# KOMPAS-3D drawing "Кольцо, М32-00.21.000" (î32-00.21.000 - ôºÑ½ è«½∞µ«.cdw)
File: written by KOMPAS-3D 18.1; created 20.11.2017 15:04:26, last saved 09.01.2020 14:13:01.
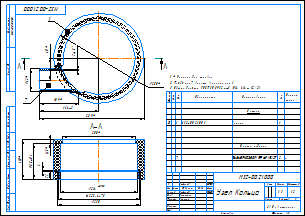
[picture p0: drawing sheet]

Sheet 1: A3, landscape

Document properties: Автор: Милов; Организация: Милов; Масса: 1.30083; Полное имя файла: М32-00.21.000 - Узел Кольцо.a3d

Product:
- Part/product: (unnamed)  | designation М32-00.21.000-01
- Part/product: Кольцо  | designation М32-00.21.000
    Масса: 1.60884
  - Component [detail]: Труба 63 PN10 S=5,8 FV PPR ф. FV PLAST  | pos. 7  | Материал: Полипропилен  ГОСТ 26996-86 (density 900 kg/m3); Масса: 0.0799362; Раздел спецификации: Прочие изделия; Примечание: м; source file: ..\..\..\..\1 ПКИ 3D\Полипропиленовые фитинги, трубы\Трубы\Труба 63 PN10 S=5,8 FV PPR ф. FV PLAST.m3d
  - Component [detail]: Кольцо  | designation М32-00.21.001  | pos. 8  | Материал: Полипропилен  ГОСТ 26996-86 (density 900 kg/m3); Масса: 1.5289; Раздел спецификации: Детали; source file: М32-00.21.001 - Кольцо.cdw, М32-00.21.001 - Кольцо.m3d
- Part/product: Узел Кольцо  | designation М32-00.21.000
    Масса: 1.30083
    source file: М32-00.21.000 - Кольцо.cdw, М32-00.21.000-01 - Кольцо.cdw
  - Component [detail]: Труба 63 PN10 S=5,8 FV PPR ф. FV PLAST  | pos. 9  | Материал: Полипропилен  ГОСТ 26996-86 (density 900 kg/m3); Масса: 0.0740283; Раздел спецификации: Прочие изделия; Примечание: м; source file: ..\..\..\..\1 ПКИ 3D\Полипропиленовые фитинги, трубы\Трубы\Труба 63 PN10 S=5,8 FV PPR ф. FV PLAST.m3d
  - Component [detail]: Кольцо  | designation М32-00.21.001  | pos. 10  | Материал: Полипропилен  ГОСТ 26996-86 (density 900 kg/m3); Масса: 1.66598; Раздел спецификации: Детали; Форматы листов документа: A3; source file: М32-00.21.001 - Кольцо.cdw, М32-00.21.001 - Кольцо.m3d
- Part/product: Кольцо  | designation М32-00.21.000  | pos. 0
    Масса: 1.28716
    Раздел спецификации: Сборочные единицы
    Форматы листов документа: A3
    source file: М32-00.21.000 - Кольцо.cdw
  - Component [detail]: Деталь  | pos. 4  | Масса: 0.0160222; Раздел спецификации: Детали; source file: ..\Стержень для позиционирования корпуса.m3d
  - Component [detail]: Труба 63 PN10 S=5,8 FV PPR ф. FV PLAST  | designation 1003  | pos. 0  | Материал: Полипропилен  ГОСТ 26996-86 (density 900 kg/m3); Масса: 0.152669; Раздел спецификации: Прочие изделия; Примечание: м
  - Component [detail]: Кольцо  | designation М40-00.21.001  | pos. 0  | Материал: Полипропилен  ГОСТ 26996-86 (density 900 kg/m3); Масса: 1.59002; Раздел спецификации: Детали; Форматы листов документа: A3; source file: ..\Магна ins 40\3Д\М40-00.21.001 - Кольцо.cdw, М32-00.21.001 - Кольцо.m3d

Title block, sheet 1: Наименование: Узел Кольцо; designation: М32-00.21.000; Масса: 1,3; scale: 1:2; Количество листов документа: 1; organisation: ЗАО «Астерион»; Форматы листов документа: A3; stored path: D:\Отработать\Магна 40\Чертежи\М40-00.21.000 - Кольцо.cdw; Разработал: Лифлянд; Проверил: Борисенко; Т. контр.: Лучихин; Разработал, date: 19.04.2019

Views: Проекционный вид 3, Местный разрез 1, Вид 4, Разрез А-А, Вид:1
Referenced files in D:\Magna\Магна Ins\Магна ins 32\Для Караби\: М32-00.21.000 - Узел Кольцо.a3d, М32-00.21.001 - Кольцо.m3d, М32-00.21.001 - Кольцо.cdw
Referenced files in D:\Отработать\Магна 40\3Д\: М40-00.21.000 - Кольцо.a3d
Referenced files in Z:\Магна\Магна Ins\Магна ins 32\: М32-00.21.000 - Кольцо.a3d, М32-00.21.001 - Кольцо.m3d
Referenced files in D:\1 ПКИ 3D\Полипропиленовые фитинги, трубы\Трубы\: Труба 63 PN10 S=5,8 FV PPR ф. FV PLAST.m3d
Referenced files in Z:\1 ПКИ 3D\Полипропиленовые фитинги, трубы\Трубы\: Труба 63 PN10 S=5,8 FV PPR ф. FV PLAST.m3d
Referenced files in \\192.168.87.28\Konstructor_doc\Магна\Магна Ins\Магна ins 32\: М32-00.21.001 - Кольцо.m3d
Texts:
  Труба 63 PN10 S=5,8 FV PPR ф. FV PLAST
  Кольцо
Dimensions and other numbers on the sheet: 63; 164±3; 289; 250; 60; 1; 7; 109; 2; 6; 110; 214; 230; 225; 22; 3; 11,5; 200; 98,5±0,1; 4; 1:2; 1,3; 19.04.2019; 12.07.2019

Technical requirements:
  * Размеры для справок.
  Трубу поз. 7  впаять в кольцо поз. 1 .
  Общие допуски ГОСТ 30893.2-mK (H14, h14,  t2/2).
